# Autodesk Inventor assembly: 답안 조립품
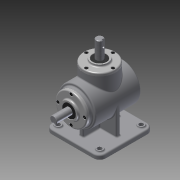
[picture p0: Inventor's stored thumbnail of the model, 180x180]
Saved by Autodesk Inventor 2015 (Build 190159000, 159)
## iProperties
Created: 2015-07
Part Number: 답안 조립품
Document SubType Name: Assembly
Designer: PHO-1
Author: PHO-1
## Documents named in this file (14)
- C:\Users\PHO-1\Desktop\450705V1024\답안 조립품.iam
- C:\Users\PHO-1\Desktop\450705V1024\본체.ipt
- C:\Users\PHO-1\Desktop\450705V1024\커버.ipt
- C:\Users\PHO-1\Desktop\450705V1024\베어링 6203.ipt
- C:\Users\PHO-1\Desktop\450705V1024\오일실.ipt
- C:\Users\PHO-1\Desktop\450705V1024\서브 축.ipt
- 서브 축.ipt
- C:\Users\PHO-1\Desktop\450705V1024\키 4x4.ipt
- C:\Users\PHO-1\Desktop\450705V1024\서브 베벨기어.ipt
- C:\Users\PHO-1\Desktop\450705V1024\메인 축.ipt
- 메인 축.ipt
- C:\Users\PHO-1\Desktop\450705V1024\키 5x5.ipt
- C:\Users\PHO-1\Desktop\450705V1024\메인 베벨기어.ipt
- C:\Users\PHO-1\Desktop\450705V1024\M4.ipt
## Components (8 placed, 1 different names)
1. M4:1 — 각도:1
2. M4:3
3. M4:4
4. M4:5
5. M4:2 — 각도:2
6. M4:6
7. M4:7
8. M4:8
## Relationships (2: Angle 2)
- 각도:1 [Angle]: M4:1
- 각도:2 [Angle]: M4:2
